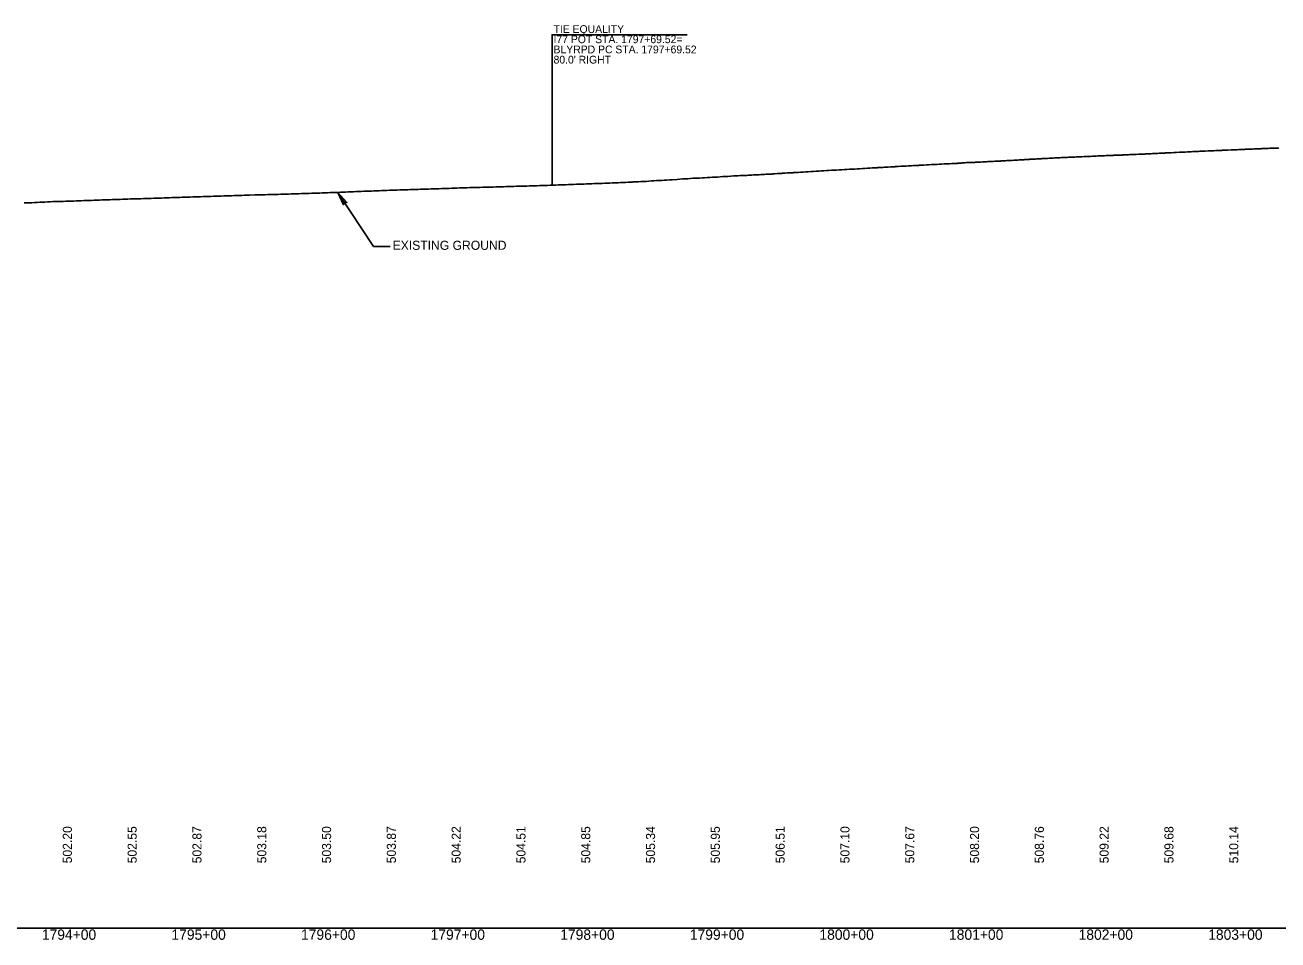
# Model space of a CAD drawing. Extents: x 2017200 to 2047700, y 854850 to 893350.
# Drawn here: x 2034363 to 2035330, y 856091 to 856797 of the extents above; entities that cross this region are included whole.
import ezdxf

# ---------------------------------------------------------------- set-up
doc = ezdxf.new("R2010")
doc.units = 0
for name, color, linetype in [('RD_DDB_Profile_EX', 7, 'Continuous'), ('RD_DDB_Profile_Lbl', 7, 'Continuous'), ('RD_DDB_StaTX', 7, 'Continuous'), ('RD_DDB_StripGrade', 7, 'Continuous'), ('RD_GPK_Profile_Cell', 7, 'Continuous')]:
    doc.layers.add(name, color=color, linetype=linetype)

msp = doc.modelspace()

# ---------------------------------------------------------------- linework, layer by layer
at = {"layer": 'RD_DDB_Profile_EX'}
msp.add_lwpolyline([(2034362.2, 856659.51), (2034364.2, 856659.6), (2034366.2, 856659.63), (2034368.2, 856659.64), (2034370.2, 856659.79), (2034372.2, 856659.9), (2034374.2, 856660), (2034376.2, 856660.08), (2034378.2, 856660.17), (2034380.2, 856660.31), (2034382.2, 856660.4), (2034384.2, 856660.48), (2034386.2, 856660.54), (2034388.2, 856660.59), (2034390.2, 856660.65), (2034392.2, 856660.72), (2034394.21, 856660.79), (2034396.21, 856660.87), (2034398.21, 856660.93), (2034400.21, 856660.99), (2034402.21, 856661.07), (2034404.21, 856661.15), (2034406.21, 856661.23), (2034408.21, 856661.29), (2034410.21, 856661.34), (2034412.19, 856661.39), (2034414.19, 856661.46), (2034416.19, 856661.53), (2034418.19, 856661.62), (2034420.22, 856661.7), (2034422.22, 856661.77), (2034424.22, 856661.84), (2034426.22, 856661.93), (2034428.22, 856662), (2034430.22, 856662.07), (2034432.22, 856662.13), (2034434.22, 856662.18), (2034436.22, 856662.24), (2034438.22, 856662.31), (2034440.22, 856662.39), (2034442.2, 856662.48), (2034444.2, 856662.55), (2034446.2, 856662.61), (2034448.2, 856662.67), (2034450.22, 856662.73), (2034452.22, 856662.79), (2034454.21, 856662.86), (2034456.21, 856662.91), (2034458.21, 856662.95), (2034460.21, 856663), (2034462.21, 856663.05), (2034464.21, 856663.11), (2034466.21, 856663.17), (2034468.21, 856663.25), (2034470.21, 856663.34), (2034472.21, 856663.43), (2034474.21, 856663.49), (2034476.21, 856663.57), (2034478.21, 856663.66), (2034480.21, 856663.71), (2034482.21, 856663.78), (2034484.21, 856663.86), (2034486.21, 856663.94), (2034488.22, 856664.01), (2034490.22, 856664.06), (2034492.22, 856664.12), (2034494.22, 856664.18), (2034496.22, 856664.25), (2034498.22, 856664.31), (2034500.22, 856664.36), (2034502.22, 856664.44), (2034504.22, 856664.5), (2034506.22, 856664.56), (2034508.22, 856664.62), (2034510.22, 856664.69), (2034512.22, 856664.75), (2034514.22, 856664.82), (2034516.22, 856664.86), (2034518.22, 856664.94), (2034520.22, 856665.01), (2034522.22, 856665.06), (2034524.22, 856665.17), (2034526.22, 856665.21), (2034528.22, 856665.27), (2034530.22, 856665.33), (2034532.22, 856665.41), (2034534.22, 856665.46), (2034536.24, 856665.49), (2034540.21, 856665.63), (2034542.19, 856665.7), (2034544.19, 856665.74), (2034546.19, 856665.81), (2034548.19, 856665.85), (2034550.19, 856665.89), (2034552.19, 856665.95), (2034554.19, 856666), (2034556.19, 856666.06), (2034558.19, 856666.09), (2034560.19, 856666.16), (2034562.19, 856666.24), (2034564.19, 856666.31), (2034566.19, 856666.36), (2034568.2, 856666.43), (2034570.2, 856666.49), (2034572.2, 856666.56), (2034574.2, 856666.64), (2034576.2, 856666.69), (2034578.2, 856666.76), (2034580.2, 856666.79), (2034582.2, 856666.87), (2034584.2, 856666.92), (2034586.2, 856667.02), (2034588.2, 856667.08), (2034590.2, 856667.14), (2034592.2, 856667.2), (2034594.2, 856667.29), (2034596.2, 856667.35), (2034598.2, 856667.44), (2034600.2, 856667.5), (2034602.2, 856667.58), (2034604.2, 856667.65), (2034606.2, 856667.74), (2034608.2, 856667.81), (2034610.2, 856667.92), (2034612.2, 856667.97), (2034614.2, 856668.06), (2034616.2, 856668.12), (2034618.2, 856668.23), (2034620.2, 856668.3), (2034622.18, 856668.4), (2034624.16, 856668.46), (2034626.1, 856668.53), (2034628.1, 856668.61), (2034630.1, 856668.7), (2034632.1, 856668.79), (2034634.1, 856668.85), (2034636.1, 856668.93), (2034638.1, 856669.01), (2034640.1, 856669.1), (2034642.1, 856669.16), (2034644.1, 856669.24), (2034646.1, 856669.3), (2034648.1, 856669.36), (2034650.1, 856669.35), (2034652.1, 856669.5), (2034654.1, 856669.58), (2034656.1, 856669.64), (2034658.1, 856669.71), (2034660.1, 856669.77), (2034662.1, 856669.83), (2034664.1, 856669.91), (2034666.1, 856669.95), (2034668.1, 856670.03), (2034670.1, 856670.08), (2034672.1, 856670.16), (2034674.1, 856670.21), (2034676.1, 856670.29), (2034678.1, 856670.35), (2034680.1, 856670.43), (2034682.1, 856670.49), (2034684.1, 856670.57), (2034686.1, 856670.62), (2034688.1, 856670.7), (2034690.1, 856670.75), (2034692.1, 856670.84), (2034694.09, 856670.89), (2034696.1, 856670.97), (2034698.1, 856671.03), (2034700.1, 856671.09), (2034702.1, 856671.17), (2034704.1, 856671.22), (2034706.1, 856671.3), (2034708.1, 856671.35), (2034710.1, 856671.41), (2034712.11, 856671.48), (2034714.11, 856671.52), (2034716.11, 856671.58), (2034718.11, 856671.64), (2034720.11, 856671.68), (2034722.11, 856671.73), (2034724.11, 856671.79), (2034726.11, 856671.84), (2034728.11, 856671.9), (2034730.11, 856671.96), (2034732.11, 856672.01), (2034734.11, 856672.06), (2034736.11, 856672.13), (2034738.11, 856672.18), (2034740.11, 856672.27), (2034742.11, 856672.34), (2034744.11, 856672.39), (2034746.11, 856672.42), (2034748.11, 856672.49), (2034750.11, 856672.53), (2034752.11, 856672.6), (2034754.11, 856672.67), (2034756.11, 856672.71), (2034758.11, 856672.77), (2034760.11, 856672.85), (2034762.11, 856672.92), (2034764.11, 856673), (2034766.11, 856673.06), (2034768.1, 856673.11), (2034768.57, 856673.14), (2034770.17, 856673.23), (2034772.1, 856673.29), (2034774.13, 856673.36), (2034774.8, 856673.38), (2034776.11, 856673.42), (2034778.11, 856673.46), (2034780.11, 856673.55), (2034782.11, 856673.63), (2034784.11, 856673.69), (2034785.2, 856673.73), (2034786.16, 856673.77), (2034788.27, 856673.85), (2034790.11, 856673.91), (2034794.35, 856674.06), (2034796.11, 856674.12), (2034798.11, 856674.21), (2034800.12, 856674.27), (2034802.12, 856674.37), (2034804.12, 856674.42), (2034806.12, 856674.5), (2034808.12, 856674.56), (2034810.12, 856674.65), (2034812.12, 856674.72), (2034814.12, 856674.8), (2034816.18, 856674.91), (2034818.2, 856674.97), (2034820.16, 856675.07), (2034820.59, 856675.08), (2034822.35, 856675.14), (2034824.08, 856675.27), (2034826.09, 856675.39), (2034828.11, 856675.5), (2034830.11, 856675.58), (2034831.36, 856675.65), (2034832.11, 856675.7), (2034834.12, 856675.78), (2034836.11, 856675.84), (2034838.08, 856675.95), (2034840.19, 856676.02), (2034842.16, 856676.15), (2034844.12, 856676.28), (2034846.12, 856676.44), (2034848.11, 856676.57), (2034850.12, 856676.69), (2034852.12, 856676.84), (2034854.13, 856676.91), (2034856.13, 856677.06), (2034858.13, 856677.16), (2034860.14, 856677.27), (2034862.21, 856677.36), (2034866.15, 856677.66), (2034868.15, 856677.86), (2034870.16, 856677.97), (2034872.16, 856678.09), (2034874.17, 856678.22), (2034876.17, 856678.35), (2034878.18, 856678.49), (2034881.27, 856678.54), (2034883.23, 856678.69), (2034885.23, 856678.83), (2034887.23, 856678.94), (2034889.23, 856679), (2034891.23, 856679.14), (2034893.24, 856679.35), (2034895.24, 856679.47), (2034897.24, 856679.48), (2034899.24, 856679.68), (2034901.24, 856679.81), (2034903.25, 856679.87), (2034905.25, 856680.01), (2034907.19, 856680.14), (2034907.52, 856680.16), (2034909.41, 856680.31), (2034910.18, 856680.35), (2034911.68, 856680.42), (2034913.17, 856680.49), (2034914.63, 856680.57), (2034915.14, 856680.59), (2034915.55, 856680.62), (2034916.39, 856680.65), (2034917.28, 856680.67), (2034918.8, 856680.73), (2034919.21, 856680.75), (2034919.68, 856680.79), (2034920.78, 856680.87), (2034921.37, 856680.88), (2034922.94, 856680.98), (2034923.76, 856681.03), (2034925.03, 856681.08), (2034925.45, 856681.1), (2034927.05, 856681.17), (2034927.82, 856681.21), (2034929.2, 856681.28), (2034930.57, 856681.35), (2034931.15, 856681.38), (2034931.72, 856681.44), (2034932.33, 856681.49), (2034933.33, 856681.52), (2034934.8, 856681.59), (2034935.23, 856681.61), (2034935.81, 856681.68), (2034936.81, 856681.74), (2034937.41, 856681.75), (2034938.97, 856681.81), (2034939.84, 856681.87), (2034941.08, 856681.98), (2034941.47, 856682.01), (2034943.09, 856682.13), (2034943.83, 856682.18), (2034945.24, 856682.26), (2034946.69, 856682.33), (2034947.18, 856682.35), (2034948.9, 856682.48), (2034949.33, 856682.51), (2034950.91, 856682.62), (2034951.24, 856682.63), (2034951.82, 856682.67), (2034952.9, 856682.72), (2034953.38, 856682.74), (2034955.28, 856682.85), (2034955.74, 856682.89), (2034957.14, 856682.99), (2034958.64, 856683.04), (2034959.15, 856683.05), (2034959.64, 856683.09), (2034961.25, 856683.2), (2034963.2, 856683.35), (2034965.27, 856683.45), (2034967.22, 856683.55), (2034969.26, 856683.69), (2034971.21, 856683.83), (2034973.22, 856683.91), (2034975.2, 856684.07), (2034975.52, 856684.09), (2034977.22, 856684.2), (2034978.48, 856684.27), (2034979.23, 856684.31), (2034981.26, 856684.41), (2034983.14, 856684.55), (2034985.25, 856684.68), (2034987.12, 856684.71), (2034989.11, 856684.88), (2034991.08, 856685.03), (2034992.01, 856685.07), (2034993.08, 856685.11), (2034995.05, 856685.22), (2034997.05, 856685.34), (2034998.96, 856685.46), (2035000.95, 856685.53), (2035002.94, 856685.66), (2035004.94, 856685.8), (2035005.54, 856685.83), (2035006.99, 856685.9), (2035008.97, 856686.02), (2035010.79, 856686.12), (2035013.03, 856686.27), (2035014.78, 856686.36), (2035016.51, 856686.46), (2035016.81, 856686.48), (2035019.07, 856686.63), (2035020.47, 856686.7), (2035020.82, 856686.72), (2035022.88, 856686.82), (2035024.83, 856686.95), (2035025.83, 856687), (2035026.61, 856687.04), (2035026.96, 856687.06), (2035028.83, 856687.16), (2035030.61, 856687.27), (2035031.12, 856687.3), (2035032.6, 856687.4), (2035033.93, 856687.47), (2035034.62, 856687.52), (2035036.63, 856687.63), (2035038.67, 856687.76), (2035039.36, 856687.79), (2035040.33, 856687.84), (2035040.65, 856687.86), (2035042.43, 856687.94), (2035042.75, 856687.95), (2035044.35, 856688.06), (2035046.13, 856688.15), (2035046.43, 856688.17), (2035046.84, 856688.19), (2035048.39, 856688.29), (2035049.99, 856688.36), (2035050.43, 856688.38), (2035052.45, 856688.49), (2035052.89, 856688.52), (2035054.4, 856688.59), (2035056.36, 856688.7), (2035058.34, 856688.8), (2035059.66, 856688.89), (2035060.23, 856688.93), (2035062.25, 856689.04), (2035064.42, 856689.17), (2035066.42, 856689.26), (2035068.16, 856689.37), (2035070.2, 856689.47), (2035072.11, 856689.56), (2035073.18, 856689.62), (2035074.07, 856689.66), (2035076.12, 856689.74), (2035078.06, 856689.85), (2035078.42, 856689.88), (2035080.16, 856689.98), (2035082.07, 856690.03), (2035082.55, 856690.07), (2035083.9, 856690.15), (2035085.12, 856690.3), (2035085.85, 856690.36), (2035086.71, 856690.4), (2035088.02, 856690.54), (2035089.23, 856690.58), (2035089.9, 856690.64), (2035091.41, 856690.67), (2035092.15, 856690.7), (2035093.48, 856690.76), (2035093.96, 856690.78), (2035095.38, 856690.78), (2035096.27, 856690.89), (2035097.51, 856690.95), (2035098.04, 856690.98), (2035099.25, 856690.97), (2035099.74, 856690.98), (2035100.24, 856691.01), (2035101.64, 856691.13), (2035103.36, 856691.24), (2035104.01, 856691.28), (2035104.65, 856691.31), (2035105.77, 856691.36), (2035107.03, 856691.4), (2035108.22, 856691.46), (2035108.98, 856691.49), (2035109.88, 856691.54), (2035111.17, 856691.62), (2035112.39, 856691.69), (2035113.26, 856691.74), (2035113.98, 856691.78), (2035115.54, 856691.85), (2035116.11, 856691.87), (2035117.48, 856691.96), (2035118.41, 856692.01), (2035119.41, 856692.08), (2035120.54, 856692.11), (2035121.67, 856692.2), (2035122.67, 856692.26), (2035123.51, 856692.31), (2035124.52, 856692.33), (2035125.82, 856692.45), (2035126.89, 856692.51), (2035127.3, 856692.54), (2035127.6, 856692.55), (2035128.98, 856692.6), (2035129.96, 856692.71), (2035131.07, 856692.77), (2035132.95, 856692.84), (2035133.35, 856692.86), (2035133.74, 856692.88), (2035134.06, 856692.91), (2035135.24, 856692.99), (2035137.1, 856693.1), (2035137.64, 856693.13), (2035138.18, 856693.15), (2035139.38, 856693.22), (2035140.83, 856693.3), (2035141.88, 856693.35), (2035142.53, 856693.39), (2035143.51, 856693.44), (2035144.73, 856693.5), (2035146.08, 856693.57), (2035146.83, 856693.62), (2035147.62, 856693.66), (2035148.88, 856693.72), (2035150.25, 856693.8), (2035151.08, 856693.85), (2035151.89, 856693.9), (2035153, 856693.95), (2035153.56, 856693.98), (2035154.36, 856694.03), (2035155.29, 856694.09), (2035156.16, 856694.13), (2035157.12, 856694.18), (2035158.02, 856694.21), (2035158.43, 856694.23), (2035159.49, 856694.32), (2035160.4, 856694.36), (2035161.24, 856694.39), (2035162.69, 856694.44), (2035163.67, 856694.51), (2035164.62, 856694.55), (2035166.96, 856694.65), (2035167.89, 856694.69), (2035168.82, 856694.74), (2035171.47, 856694.81), (2035173.01, 856694.91), (2035174.01, 856694.95), (2035174.65, 856694.97), (2035175.92, 856695.01), (2035177.18, 856695.08), (2035178.2, 856695.13), (2035179.97, 856695.21), (2035180.31, 856695.22), (2035181.42, 856695.27), (2035182.39, 856695.33), (2035184.24, 856695.41), (2035184.65, 856695.42), (2035185.07, 856695.45), (2035186.57, 856695.51), (2035188.48, 856695.59), (2035188.96, 856695.62), (2035189.45, 856695.64), (2035190.74, 856695.72), (2035191.44, 856695.72), (2035192.72, 856695.78), (2035193.25, 856695.81), (2035193.79, 856695.83), (2035194.94, 856695.88), (2035195.89, 856695.92), (2035197.03, 856695.98), (2035197.5, 856696), (2035198.1, 856696.04), (2035199.05, 856696.06), (2035200.34, 856696.11), (2035201.35, 856696.16), (2035201.71, 856696.18), (2035202.38, 856696.21), (2035203.03, 856696.24), (2035203.84, 856696.26), (2035204.79, 856696.29), (2035205.68, 856696.33), (2035206.65, 856696.39), (2035207.33, 856696.42), (2035208.48, 856696.46), (2035209.49, 856696.48), (2035210.01, 856696.51), (2035210.9, 856696.58), (2035211.61, 856696.61), (2035212.62, 856696.64), (2035213.9, 856696.67), (2035214.35, 856696.7), (2035215.24, 856696.75), (2035215.87, 856696.78), (2035216.76, 856696.81), (2035218.11, 856696.82), (2035218.7, 856696.86), (2035220.12, 856696.98), (2035222.03, 856697.03), (2035222.72, 856697.05), (2035223.05, 856697.08), (2035224.36, 856697.18), (2035225.14, 856697.2), (2035226.55, 856697.25), (2035227.41, 856697.29), (2035228.77, 856697.38), (2035229.39, 856697.4), (2035230.36, 856697.44), (2035231.42, 856697.45), (2035231.77, 856697.47), (2035232.81, 856697.56), (2035233.63, 856697.6), (2035236.14, 856697.69), (2035237.02, 856697.75), (2035237.86, 856697.8), (2035240.52, 856697.89), (2035242.3, 856698.01), (2035242.94, 856698.05), (2035244.91, 856698.11), (2035246.3, 856698.22), (2035247.17, 856698.27), (2035249.3, 856698.35), (2035250.51, 856698.43), (2035251.39, 856698.48), (2035253.7, 856698.55), (2035254.72, 856698.65), (2035255.82, 856698.7), (2035258.11, 856698.78), (2035259.81, 856698.9), (2035260.7, 856698.94), (2035262.59, 856699.01), (2035264.02, 856699.1), (2035264.92, 856699.14), (2035266.94, 856699.21), (2035268.23, 856699.28), (2035269.35, 856699.33), (2035271.36, 856699.4), (2035272.45, 856699.48), (2035273.34, 856699.53), (2035275.79, 856699.59), (2035276.12, 856699.61), (2035277.55, 856699.71), (2035278.43, 856699.74), (2035280.24, 856699.78), (2035281.76, 856699.89), (2035282.88, 856699.93), (2035284.68, 856699.99), (2035285.97, 856700.08), (2035286.85, 856700.12), (2035287.73, 856700.16), (2035289.13, 856700.23), (2035289.65, 856700.26), (2035290.18, 856700.28), (2035291.06, 856700.33), (2035293.6, 856700.41), (2035295.27, 856700.51), (2035296.41, 856700.53), (2035297.41, 856700.56), (2035298.06, 856700.58), (2035299.49, 856700.67), (2035300.34, 856700.7), (2035301.36, 856700.75), (2035302.54, 856700.81), (2035303.18, 856700.83), (2035303.72, 856700.85), (2035304.55, 856700.88), (2035305.49, 856700.92), (2035306.7, 856700.98), (2035307.02, 856701), (2035307.96, 856701.05), (2035308.76, 856701.07), (2035309.63, 856701.09), (2035309.94, 856701.1), (2035311.13, 856701.13), (2035311.51, 856701.15), (2035312.21, 856701.2), (2035312.99, 856701.23), (2035314.72, 856701.27), (2035315.56, 856701.29), (2035316, 856701.32), (2035316.7, 856701.36), (2035317.22, 856701.39), (2035317.97, 856701.43), (2035319.1, 856701.47), (2035319.75, 856701.49), (2035320.51, 856701.53), (2035321.48, 856701.59), (2035322.19, 856701.61), (2035323.47, 856701.66), (2035324.15, 856701.67), (2035325.02, 856701.7), (2035325.75, 856701.74), (2035326.42, 856701.75), (2035327.4, 856701.78), (2035328.55, 856701.82), (2035329.54, 856701.88), (2035330.23, 856701.93)], dxfattribs=at)
at = {"layer": 'RD_DDB_Profile_Lbl'}
for p, q in [((2034631.66, 856625.93), (2034604.2, 856667.65)), ((2034644.52, 856625.93), (2034631.66, 856625.93))]:
    msp.add_line(p, q, dxfattribs=at)
msp.add_lwpolyline([(2034769.52, 856673.19), (2034769.52, 856789.29), (2034873.84, 856789.29)], dxfattribs=at)
msp.add_lwpolyline([(2034604.2, 856667.65), (2034608.66, 856658.15), (2034609.03, 856660.31), (2034611.17, 856659.8)], close=True, dxfattribs=at)
at = {"layer": 'RD_GPK_Profile_Cell'}
msp.add_line((2020500, 856100), (2047700, 856100), dxfattribs=at)

# ---------------------------------------------------------------- texts
at = {"layer": 'RD_DDB_Profile_Lbl'}
for s, height, p in [('TIE EQUALITY', 6, (2034770.65, 856790.64)), ('I77 POT STA. 1797+69.52=', 6, (2034770.65, 856782.77)), ('BLYRPD PC STA. 1797+69.52', 6, (2034770.65, 856774.91)), ("80.0' RIGHT", 6, (2034770.65, 856767.04)), ('EXISTING GROUND', 7, (2034646.46, 856623.32))]:
    msp.add_text(s, height=height, dxfattribs=at).set_placement(p)
at = {"layer": 'RD_DDB_StaTX'}
for s, p in [('1794+00', (2034375.8, 856091)), ('1795+00', (2034475.8, 856091)), ('1796+00', (2034575.8, 856091)), ('1797+00', (2034675.8, 856091)), ('1798+00', (2034775.8, 856091)), ('1799+00', (2034875.8, 856091)), ('1800+00', (2034975.8, 856091)), ('1801+00', (2035075.8, 856091)), ('1802+00', (2035175.8, 856091)), ('1803+00', (2035275.8, 856091))]:
    msp.add_text(s, height=8, dxfattribs=at).set_placement(p)
at = {"layer": 'RD_DDB_StripGrade'}
for s, p in [('502.20', (2034399, 856150)), ('502.55', (2034449, 856150)), ('502.87', (2034499, 856150)), ('503.18', (2034549, 856150)), ('503.50', (2034599, 856150)), ('503.87', (2034649, 856150)), ('504.22', (2034699, 856150)), ('504.51', (2034749, 856150)), ('504.85', (2034799, 856150)), ('505.34', (2034849, 856150)), ('505.95', (2034899, 856150)), ('506.51', (2034949, 856150)), ('507.10', (2034999, 856150)), ('507.67', (2035049, 856150)), ('508.20', (2035099, 856150)), ('508.76', (2035149, 856150)), ('509.22', (2035199, 856150)), ('509.68', (2035249, 856150)), ('510.14', (2035299, 856150))]:
    msp.add_text(s, height=7, rotation=90, dxfattribs=at).set_placement(p)

doc.saveas('drawing.dxf')
